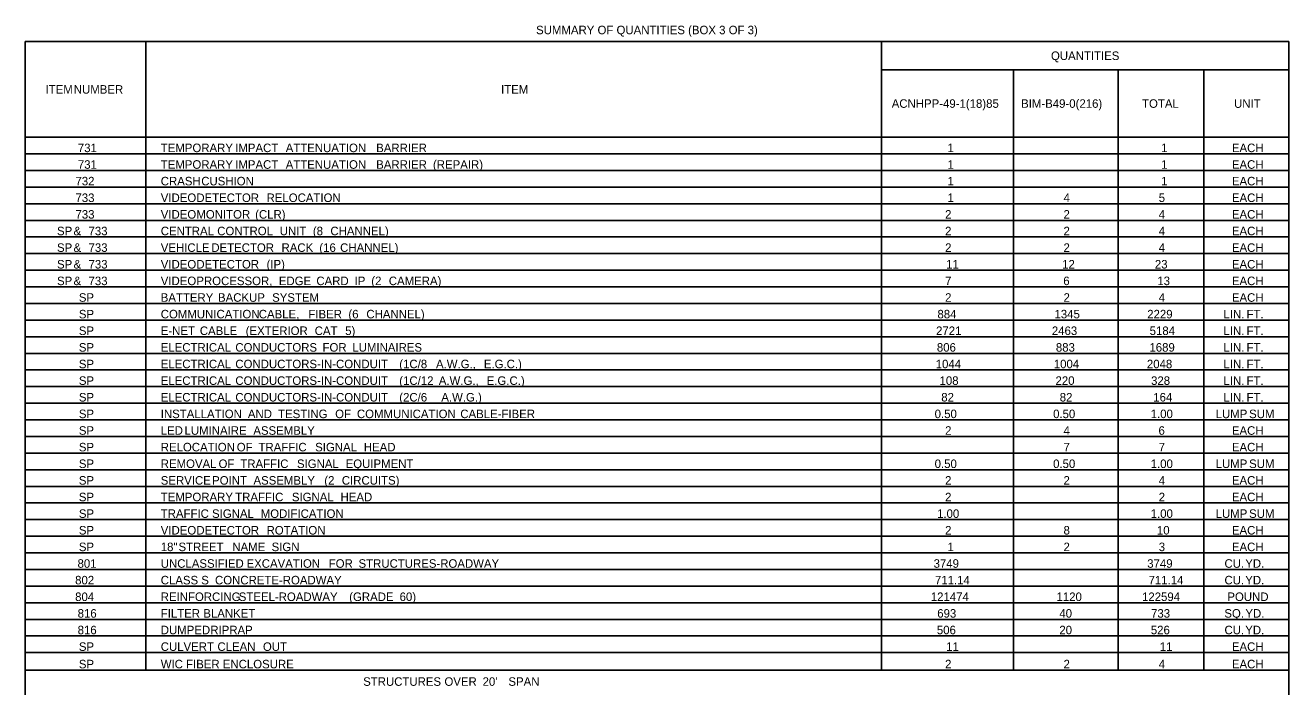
# Model space of a CAD drawing. Extents: x 1226912 to 1228117, y 151309 to 152323.
# Drawn here: x 1226912 to 1227653, y 151863 to 152250 of the extents above; entities that cross this region are included whole.
import ezdxf

# ---------------------------------------------------------------- set-up
doc = ezdxf.new("R2010")
doc.units = 0
doc.layers.add('R_Dimension', color=7, linetype='Continuous')

msp = doc.modelspace()

# ---------------------------------------------------------------- linework, layer by layer
at = {"layer": 'R_Dimension'}
for p, q in [((1226912.03, 152240.88), (1227653.03, 152240.88)), ((1226912.03, 152184.82), (1226912.03, 152240.88)), ((1226982.72, 152184.82), (1226982.72, 152240.88)), ((1227414.15, 152184.82), (1227414.15, 152240.88)), ((1227653.03, 152184.82), (1227653.03, 152240.88)), ((1227414.15, 152224.3), (1227653.03, 152224.3)), ((1227491.67, 152184.82), (1227491.67, 152224.3)), ((1227553.09, 152184.82), (1227553.09, 152224.3)), ((1227603.3, 152184.82), (1227603.3, 152224.3)), ((1226912.03, 152184.82), (1227653.03, 152184.82)), ((1226912.03, 152184.82), (1227653.03, 152184.82)), ((1226912.03, 151569.59), (1226912.03, 152184.82)), ((1226982.72, 151872.33), (1226982.72, 152184.82)), ((1227414.15, 151872.33), (1227414.15, 152184.82)), ((1227491.67, 151872.33), (1227491.67, 152184.82)), ((1227553.09, 151872.33), (1227553.09, 152184.82)), ((1227603.3, 151872.33), (1227603.3, 152184.82)), ((1227653.03, 151569.59), (1227653.03, 152184.82)), ((1226912.03, 152175.07), (1227653.03, 152175.07)), ((1226912.03, 152165.32), (1227653.03, 152165.32)), ((1226912.03, 152155.57), (1227653.03, 152155.57)), ((1226912.03, 152145.82), (1227653.03, 152145.82)), ((1226912.03, 152136.07), (1227653.03, 152136.07)), ((1226912.03, 152126.32), (1227653.03, 152126.32)), ((1226912.03, 152116.57), (1227653.03, 152116.57)), ((1226912.03, 152106.82), (1227653.03, 152106.82)), ((1226912.03, 152097.07), (1227653.03, 152097.07)), ((1226912.03, 152087.32), (1227653.03, 152087.32)), ((1226912.03, 152077.57), (1227653.03, 152077.57)), ((1226912.03, 152067.82), (1227653.03, 152067.82)), ((1226912.03, 152058.07), (1227653.03, 152058.07)), ((1226912.03, 152048.32), (1227653.03, 152048.32)), ((1226912.03, 152038.57), (1227653.03, 152038.57)), ((1226912.03, 152028.82), (1227653.03, 152028.82)), ((1226912.03, 152019.07), (1227653.03, 152019.07)), ((1226912.03, 152009.32), (1227653.03, 152009.32)), ((1226912.03, 151999.57), (1227653.03, 151999.57)), ((1226912.03, 151989.82), (1227653.03, 151989.82)), ((1226912.03, 151980.07), (1227653.03, 151980.07)), ((1226912.03, 151970.32), (1227653.03, 151970.32)), ((1226912.03, 151960.57), (1227653.03, 151960.57)), ((1226912.03, 151950.82), (1227653.03, 151950.82)), ((1226912.03, 151941.07), (1227653.03, 151941.07)), ((1226912.03, 151931.32), (1227653.03, 151931.32)), ((1226912.03, 151921.57), (1227653.03, 151921.57)), ((1226912.03, 151911.82), (1227653.03, 151911.82)), ((1226912.03, 151902.07), (1227653.03, 151902.07)), ((1226912.03, 151892.32), (1227653.03, 151892.32)), ((1226912.03, 151882.57), (1227653.03, 151882.57)), ((1226912.03, 151872.33), (1227653.03, 151872.33))]:
    msp.add_line(p, q, dxfattribs=at)

# ---------------------------------------------------------------- texts
for s, p in [('SUMMARY OF QUANTITIES (BOX 3 OF 3)', (1227211.62, 152245.2)), ('QUANTITIES', (1227513.59, 152230.09)), ('ITEM', (1226923.91, 152210.35)), (' NUMBER', (1226938.63, 152210.35)), ('ITEM', (1227191.07, 152210.35)), ('ACNHPP-49-1(18)85', (1227420.19, 152202.06)), ('BIM-B49-0(216)', (1227496.08, 152202.06)), ('TOTAL', (1227567.02, 152202.06)), ('UNIT', (1227620.94, 152202.06)), ('731', (1226942.88, 152176.07)), ('TEMPORARY', (1226991.49, 152176.07)), (' IMPACT', (1227033.3, 152176.07)), (' ATTENUATION', (1227062.91, 152176.07)), (' BARRIER', (1227115.98, 152176.07)), ('1', (1227452.91, 152176.07)), ('1', (1227578.2, 152176.07)), ('EACH', (1227619.7, 152176.07)), ('731', (1226942.88, 152166.32)), ('TEMPORARY', (1226991.49, 152166.32)), (' IMPACT', (1227033.3, 152166.32)), (' ATTENUATION', (1227062.91, 152166.32)), (' BARRIER', (1227115.98, 152166.32)), (' (REPAIR)', (1227149.29, 152166.32)), ('1', (1227452.91, 152166.32)), ('1', (1227578.2, 152166.32)), ('EACH', (1227619.7, 152166.32)), ('732', (1226941.47, 152156.57)), ('CRASH', (1226991.49, 152156.57)), (' CUSHION', (1227013.38, 152156.57)), ('1', (1227452.91, 152156.57)), ('1', (1227578.2, 152156.57)), ('EACH', (1227619.7, 152156.57)), ('733', (1226941.47, 152146.82)), ('VIDEO', (1226991.49, 152146.82)), (' DETECTOR', (1227010.51, 152146.82)), (' RELOCATION', (1227051.69, 152146.82)), ('1', (1227452.91, 152146.82)), ('4', (1227520.96, 152146.82)), ('5', (1227576.78, 152146.82)), ('EACH', (1227619.7, 152146.82)), ('733', (1226941.47, 152137.07)), ('VIDEO', (1226991.49, 152137.07)), (' MONITOR', (1227010.51, 152137.07)), (' (CLR)', (1227045, 152137.07)), ('2', (1227451.49, 152137.07)), ('2', (1227520.96, 152137.07)), ('EACH', (1227619.7, 152137.07)), ('4', (1227576.78, 152137.07)), ('SP', (1226930.66, 152127.32)), (' &', (1226938.5, 152127.32)), (' 733', (1226947.27, 152127.32)), ('CENTRAL', (1226991.49, 152127.32)), (' CONTROL', (1227022.75, 152127.32)), (' UNIT', (1227059.41, 152127.32)), (' (8', (1227078.85, 152127.32)), (' CHANNEL)', (1227089.13, 152127.32)), ('2', (1227451.49, 152127.32)), ('2', (1227520.96, 152127.32)), ('4', (1227576.78, 152127.32)), ('EACH', (1227619.7, 152127.32)), ('SP', (1226930.66, 152117.57)), (' &', (1226938.5, 152117.57)), (' 733', (1226947.27, 152117.57)), ('VEHICLE', (1226991.49, 152117.57)), (' DETECTOR', (1227019.29, 152117.57)), (' RACK', (1227060.47, 152117.57)), (' (16', (1227082.63, 152117.57)), (' CHANNEL)', (1227094.84, 152117.57)), ('2', (1227451.49, 152117.57)), ('2', (1227520.96, 152117.57)), ('4', (1227576.78, 152117.57)), ('EACH', (1227619.7, 152117.57)), ('SP', (1226930.66, 152107.82)), (' &', (1226938.5, 152107.82)), (' 733', (1226947.27, 152107.82)), ('VIDEO', (1226991.49, 152107.82)), (' DETECTOR', (1227010.51, 152107.82)), (' (IP)', (1227051.69, 152107.82)), ('11', (1227452.08, 152107.82)), ('12', (1227520.14, 152107.82)), ('23', (1227574.54, 152107.82)), ('EACH', (1227619.7, 152107.82)), ('SP', (1226930.66, 152098.07)), (' &', (1226938.5, 152098.07)), (' 733', (1226947.27, 152098.07)), ('VIDEO', (1226991.49, 152098.07)), (' PROCESSOR,', (1227010.51, 152098.07)), (' EDGE', (1227058.89, 152098.07)), (' CARD', (1227080.9, 152098.07)), (' IP', (1227103.34, 152098.07)), (' (2', (1227113.11, 152098.07)), (' CAMERA)', (1227123.38, 152098.07)), ('7', (1227451.49, 152098.07)), ('6', (1227520.82, 152098.07)), ('13', (1227575.95, 152098.07)), ('EACH', (1227619.7, 152098.07)), ('SP', (1226943.46, 152088.32)), ('BATTERY', (1226991.49, 152088.32)), (' BACKUP', (1227023.22, 152088.32)), (' SYSTEM', (1227054.96, 152088.32)), ('2', (1227451.49, 152088.32)), ('2', (1227520.96, 152088.32)), ('4', (1227576.78, 152088.32)), ('EACH', (1227619.7, 152088.32)), ('SP', (1226943.46, 152078.57)), ('COMMUNICATION', (1226991.49, 152078.57)), (' CABLE,', (1227047.12, 152078.57)), (' FIBER', (1227076.22, 152078.57)), (' (6', (1227099.68, 152078.57)), (' CHANNEL)', (1227110.23, 152078.57)), ('884', (1227447.01, 152078.57)), ('1345', (1227515.65, 152078.57)), ('2229', (1227570.03, 152078.57)), ('LIN.', (1227614.76, 152078.57)), (' FT.', (1227626.41, 152078.57)), ('SP', (1226943.46, 152068.82)), ('E-NET', (1226991.49, 152068.82)), (' CABLE', (1227012.55, 152068.82)), (' (EXTERIOR', (1227039.44, 152068.82)), (' CAT', (1227079.92, 152068.82)), (' 5)', (1227097.79, 152068.82)), ('2721', (1227446.18, 152068.82)), ('2463', (1227514.11, 152068.82)), ('5184', (1227571.47, 152068.82)), ('LIN.', (1227614.76, 152068.82)), (' FT.', (1227626.41, 152068.82)), ('SP', (1226943.46, 152059.07)), ('ELECTRICAL', (1226991.49, 152059.07)), (' CONDUCTORS', (1227033.38, 152059.07)), (' FOR', (1227084.52, 152059.07)), (' LUMINAIRES', (1227102, 152059.07)), ('806', (1227446.67, 152059.07)), ('883', (1227516.47, 152059.07)), ('1689', (1227571.33, 152059.07)), ('LIN.', (1227614.76, 152059.07)), (' FT.', (1227626.41, 152059.07)), ('SP', (1226943.46, 152049.32)), ('ELECTRICAL', (1226991.49, 152049.32)), (' CONDUCTORS-IN-CONDUIT', (1227033.38, 152049.32)), (' (1C/8', (1227129.52, 152049.32)), (' A.W.G.,', (1227151.06, 152049.32)), (' E.G.C.)', (1227179.13, 152049.32)), ('1044', (1227445.98, 152049.32)), ('1004', (1227515.25, 152049.32)), ('2048', (1227569.85, 152049.32)), ('LIN.', (1227614.76, 152049.32)), (' FT.', (1227626.41, 152049.32)), ('SP', (1226943.46, 152039.57)), ('ELECTRICAL', (1226991.49, 152039.57)), (' CONDUCTORS-IN-CONDUIT', (1227033.38, 152039.57)), (' (1C/12', (1227129.52, 152039.57)), (' A.W.G.,', (1227152.71, 152039.57)), (' E.G.C.)', (1227180.78, 152039.57)), ('108', (1227448.23, 152039.57)), ('220', (1227516.26, 152039.57)), ('328', (1227572.29, 152039.57)), ('LIN.', (1227614.76, 152039.57)), (' FT.', (1227626.41, 152039.57)), ('SP', (1226943.46, 152029.82)), ('ELECTRICAL', (1226991.49, 152029.82)), (' CONDUCTORS-IN-CONDUIT', (1227033.38, 152029.82)), (' (2C/6', (1227129.52, 152029.82)), (' A.W.G.)', (1227154.17, 152029.82)), ('82', (1227449.25, 152029.82)), ('82', (1227518.72, 152029.82)), ('164', (1227573.59, 152029.82)), ('LIN.', (1227614.76, 152029.82)), (' FT.', (1227626.41, 152029.82)), ('SP', (1226943.46, 152020.07)), ('INSTALLATION', (1226991.49, 152020.07)), (' AND', (1227040.74, 152020.07)), (' TESTING', (1227058.46, 152020.07)), (' OF', (1227091.92, 152020.07)), (' COMMUNICATION', (1227104.68, 152020.07)), (' CABLE-FIBER', (1227165.31, 152020.07)), ('0.50', (1227445.37, 152020.07)), ('0.50', (1227514.84, 152020.07)), ('1.00', (1227572.08, 152020.07)), ('LUMP', (1227610.17, 152020.07)), (' SUM', (1227627.93, 152020.07)), ('SP', (1226943.46, 152010.32)), ('LED', (1226991.49, 152010.32)), (' LUMINAIRE', (1227003.58, 152010.32)), (' ASSEMBLY', (1227043.93, 152010.32)), ('2', (1227451.49, 152010.32)), ('4', (1227520.96, 152010.32)), ('6', (1227576.64, 152010.32)), ('EACH', (1227619.7, 152010.32)), ('SP', (1226943.46, 152000.57)), ('RELOCATION', (1226991.49, 152000.57)), (' OF', (1227034.21, 152000.57)), (' TRAFFIC', (1227046.96, 152000.57)), (' SIGNAL', (1227080.19, 152000.57)), (' HEAD', (1227108.74, 152000.57)), ('7', (1227520.96, 152000.57)), ('7', (1227576.78, 152000.57)), ('EACH', (1227619.7, 152000.57)), ('SP', (1226943.46, 151990.82)), ('REMOVAL', (1226991.49, 151990.82)), (' OF', (1227023.54, 151990.82)), (' TRAFFIC', (1227036.3, 151990.82)), (' SIGNAL', (1227069.52, 151990.82)), (' EQUIPMENT', (1227098.07, 151990.82)), ('0.50', (1227445.37, 151990.82)), ('0.50', (1227514.84, 151990.82)), ('1.00', (1227572.08, 151990.82)), ('LUMP', (1227610.17, 151990.82)), (' SUM', (1227627.93, 151990.82)), ('SP', (1226943.46, 151981.07)), ('SERVICE', (1226991.49, 151981.07)), (' POINT', (1227019.76, 151981.07)), (' ASSEMBLY', (1227044.01, 151981.07)), (' (2', (1227085.55, 151981.07)), (' CIRCUITS)', (1227095.82, 151981.07)), ('2', (1227451.49, 151981.07)), ('2', (1227520.96, 151981.07)), ('4', (1227576.78, 151981.07)), ('EACH', (1227619.7, 151981.07)), ('SP', (1226943.46, 151971.32)), ('TEMPORARY', (1226991.49, 151971.32)), (' TRAFFIC', (1227033.3, 151971.32)), (' SIGNAL', (1227066.53, 151971.32)), (' HEAD', (1227095.07, 151971.32)), ('2', (1227451.49, 151971.32)), ('2', (1227576.78, 151971.32)), ('EACH', (1227619.7, 151971.32)), ('SP', (1226943.46, 151961.57)), ('TRAFFIC', (1226991.49, 151961.57)), (' SIGNAL', (1227019.72, 151961.57)), (' MODIFICATION', (1227048.26, 151961.57)), ('1.00', (1227446.79, 151961.57)), ('1.00', (1227572.08, 151961.57)), ('LUMP', (1227610.17, 151961.57)), (' SUM', (1227627.93, 151961.57)), ('SP', (1226943.46, 151951.82)), ('VIDEO', (1226991.49, 151951.82)), (' DETECTOR', (1227010.51, 151951.82)), (' ROTATION', (1227051.69, 151951.82)), ('2', (1227451.49, 151951.82)), ('8', (1227520.96, 151951.82)), ('10', (1227575.74, 151951.82)), ('EACH', (1227619.7, 151951.82)), ('SP', (1226943.46, 151942.07)), ('18"', (1226991.49, 151942.07)), (' STREET', (1227000.04, 151942.07)), (' NAME', (1227031.61, 151942.07)), (' SIGN', (1227054.64, 151942.07)), ('1', (1227452.91, 151942.07)), ('2', (1227520.96, 151942.07)), ('3', (1227576.78, 151942.07)), ('EACH', (1227619.7, 151942.07)), ('801', (1226942.69, 151932.32)), ('UNCLASSIFIED', (1226991.49, 151932.32)), (' EXCAVATION', (1227039.96, 151932.32)), (' FOR', (1227088.15, 151932.32)), (' STRUCTURES-ROADWAY', (1227105.63, 151932.32)), ('3749', (1227444.74, 151932.32)), ('3749', (1227570.03, 151932.32)), ('CU.', (1227615.35, 151932.32)), (' YD.', (1227625.67, 151932.32)), ('802', (1226941.27, 151922.57)), ('CLASS', (1226991.49, 151922.57)), (' S', (1227013.38, 151922.57)), (' CONCRETE-ROADWAY', (1227021.45, 151922.57)), ('711.14', (1227445.55, 151922.57)), ('711.14', (1227570.84, 151922.57)), ('CU.', (1227615.35, 151922.57)), (' YD.', (1227625.67, 151922.57)), ('804', (1226941.27, 151912.82)), ('REINFORCING', (1226991.49, 151912.82)), (' STEEL-ROADWAY', (1227035.39, 151912.82)), (' (GRADE', (1227100.15, 151912.82)), (' 60)', (1227129.72, 151912.82)), ('121474', (1227443.11, 151912.82)), ('1120', (1227516.85, 151912.82)), ('122594', (1227566.98, 151912.82)), ('POUND', (1227617.04, 151912.82)), ('816', (1226942.75, 151903.07)), ('FILTER', (1226991.49, 151903.07)), (' BLANKET', (1227014.6, 151903.07)), ('693', (1227446.89, 151903.07)), ('40', (1227518.5, 151903.07)), ('733', (1227572.29, 151903.07)), ('SQ.', (1227615.27, 151903.07)), (' YD.', (1227625.75, 151903.07)), ('816', (1226942.75, 151893.32)), ('DUMPED', (1226991.49, 151893.32)), (' RIPRAP', (1227018.7, 151893.32)), ('506', (1227446.67, 151893.32)), ('20', (1227518.5, 151893.32)), ('526', (1227572.15, 151893.32)), ('CU.', (1227615.35, 151893.32)), (' YD.', (1227625.67, 151893.32)), ('SP', (1226943.46, 151883.57)), ('CULVERT', (1226991.49, 151883.57)), (' CLEAN', (1227022.87, 151883.57)), (' OUT', (1227049.56, 151883.57)), ('11', (1227452.08, 151883.57)), ('11', (1227577.37, 151883.57)), ('EACH', (1227619.7, 151883.57)), ('SP', (1226943.46, 151873.33)), ('WIC FIBER ENCLOSURE', (1226991.49, 151873.33)), ('2', (1227451.49, 151873.33)), ('2', (1227520.96, 151873.33)), ('4', (1227576.78, 151873.33)), ('EACH', (1227619.7, 151873.33)), ('STRUCTURES', (1227110.2, 151863.09)), (' OVER', (1227156.02, 151863.09)), (" 20'", (1227178.39, 151863.09)), (' SPAN', (1227193.54, 151863.09))]:
    msp.add_text(s, height=5, dxfattribs=at).set_placement(p)

doc.saveas('drawing.dxf')
